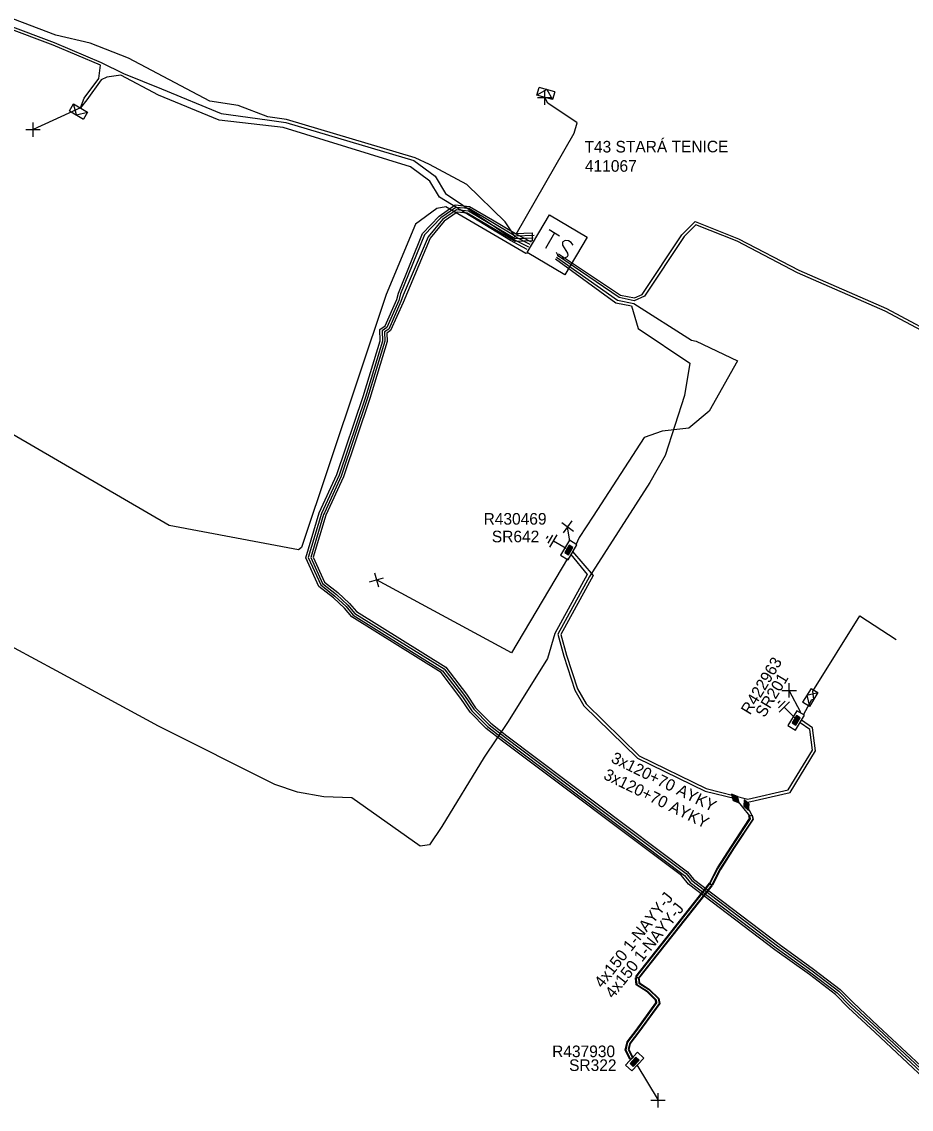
# Model space of a CAD drawing. Extents: x -540466 to -537383, y -1184038 to -1179972.
# Drawn here: x -538183.7 to -538107, y -1180908.9 to -1180815.2 of the extents above; entities that cross this region are included whole.
import ezdxf

# ---------------------------------------------------------------- set-up
doc = ezdxf.new("R2010")
doc.units = 0
for name, color, linetype in [('Vrstva 1', 7, 'Continuous'), ('Vrstva 14', 7, 'Continuous'), ('Vrstva 15', 7, 'Continuous'), ('Vrstva 19', 7, 'Continuous'), ('Vrstva 20', 7, 'Continuous'), ('Vrstva 25', 7, 'Continuous'), ('Vrstva 26', 7, 'Continuous'), ('Vrstva 27', 7, 'Continuous'), ('Vrstva 28', 7, 'Continuous'), ('Vrstva 29', 7, 'Continuous'), ('Vrstva 30', 7, 'Continuous'), ('Vrstva 31', 7, 'Continuous'), ('Vrstva 34', 7, 'Continuous'), ('Vrstva 4', 7, 'Continuous'), ('Vrstva 5', 7, 'Continuous'), ('Vrstva 52', 7, 'Continuous'), ('Vrstva 59', 7, 'Continuous'), ('Vrstva 6', 7, 'Continuous'), ('Vrstva 8', 7, 'Continuous'), ('Vrstva 9', 7, 'Continuous')]:
    doc.layers.add(name, color=color, linetype=linetype)

# ---------------------------------------------------------------- blocks, each defined once
blk = doc.blocks.new('NN870')
at = {"layer": 'Vrstva 4'}
for points in [[(0, -0.251), (0.5, 0.001), (0, 0.249), (-0.5, 0.001), (0, -0.251)], [(0.37, -0.003), (0, 0.186), (-0.362, 0.001), (0, -0.188), (0.37, -0.003)], [(0.245, -0.003), (0, 0.123), (-0.252, -0.003), (0, -0.125), (0.245, -0.003)], [(0.122, -0.003), (0, 0.06), (-0.13, -0.003), (0, -0.062), (0.122, -0.003)]]:
    blk.add_lwpolyline(points, dxfattribs=at)
blk = doc.blocks.new('NN800')
at = {"layer": 'Vrstva 1'}
for points in [[(-0.442, 0.442), (0.442, -0.442)], [(-0.442, -0.442), (0.442, 0.442)]]:
    blk.add_lwpolyline(points, dxfattribs=at)
blk = doc.blocks.new('NN620')
at = {"layer": 'Vrstva 8'}
for points in [[(0.752, 0.004), (-0.748, 0.004)], [(-0.748, 0.004), (-0.748, -0.746)], [(0.752, -0.746), (0.752, 0.004)], [(-0.748, -0.746), (0.752, -0.746)], [(0.368, -0.18), (-0.376, -0.18)], [(-0.376, -0.18), (-0.376, -0.558)], [(-0.376, -0.558), (0.368, -0.558)], [(0.321, -0.227), (-0.329, -0.227)], [(-0.329, -0.227), (-0.329, -0.51)], [(-0.329, -0.51), (0.321, -0.51)], [(0.274, -0.274), (-0.281, -0.274)], [(-0.281, -0.274), (-0.281, -0.463)], [(-0.281, -0.463), (0.274, -0.463)], [(0.227, -0.321), (-0.234, -0.321)], [(-0.234, -0.321), (-0.234, -0.416)], [(-0.234, -0.416), (0.227, -0.416)], [(-0.193, -0.369), (0.185, -0.369)], [(0.227, -0.416), (0.227, -0.321)], [(0.274, -0.463), (0.274, -0.274)], [(0.321, -0.51), (0.321, -0.227)], [(0.368, -0.558), (0.368, -0.18)]]:
    blk.add_lwpolyline(points, dxfattribs=at)
blk = doc.blocks.new('NN630')
at = {"layer": 'Vrstva 9'}
for points in [[(-0.003, -0.7), (-0.703, 0)], [(-0.703, -0.7), (-0.703, 0), (0.697, 0), (0.697, -0.7)], [(-0.703, -0.7), (0.697, -0.7)], [(-0.003, -0.7), (0.697, 0)]]:
    blk.add_lwpolyline(points, dxfattribs=at)
blk = doc.blocks.new('NN810')
at = {"layer": 'Vrstva 14'}
for points in [[(0.004, -0.64), (0.004, -1.89)], [(0.629, -1.89), (-0.621, -1.89)], [(0.388, -2.2), (-0.399, -2.2)], [(0.004, -2.515), (-0.124, -2.515)], [(0.137, -2.515), (0.004, -2.515)]]:
    blk.add_lwpolyline(points, dxfattribs=at)
blk = doc.blocks.new('NN640')
at = {"layer": 'Vrstva 6'}
for points in [[(-1.89, 1.889), (1.889, 1.889)], [(-1.89, -1.89), (-1.89, 1.889)], [(1.889, 1.889), (1.889, -1.89)], [(-1.26, 0.787), (-0.221, 0.787)], [(-0.725, 0.787), (-0.725, -0.788)], [(1.197, 0.661), (0.945, 0.787), (0.661, 0.787), (0.409, 0.661), (0.283, 0.472), (0.283, 0.409), (0.409, 0.22), (1.133, -0.158), (1.259, -0.316), (1.259, -0.473), (1.133, -0.662), (0.913, -0.788), (0.629, -0.788), (0.503, -0.725), (0.283, -0.599)], [(1.889, -1.89), (-1.89, -1.89)]]:
    blk.add_lwpolyline(points, dxfattribs=at)

msp = doc.modelspace()

# ---------------------------------------------------------------- linework, layer by layer
at = {"layer": 'Vrstva 20'}
msp.add_lwpolyline([(-538105.459, -1180906.69), (-538110.094, -1180902.33), (-538112.43, -1180900.175), (-538113.51, -1180899.055), (-538115.769, -1180897.331), (-538118.749, -1180895.181), (-538126.19, -1180889.528), (-538126.806, -1180888.797), (-538142.223, -1180877.218), (-538143.65, -1180876.105), (-538145.023, -1180874.711), (-538145.833, -1180873.515), (-538147.535, -1180871.285), (-538155.231, -1180866.498), (-538155.849, -1180865.747), (-538156.815, -1180864.858), (-538158.063, -1180863.87), (-538159.19, -1180861.402), (-538158.032, -1180857.524), (-538156.509, -1180854.209), (-538154.245, -1180847.498), (-538152.782, -1180842.691), (-538152.816, -1180841.724), (-538152.359, -1180841.419), (-538151.35, -1180839.148), (-538151.207, -1180838.588), (-538149.122, -1180833.444), (-538147.681, -1180831.951), (-538146.312, -1180830.991), (-538145.075, -1180831.108), (-538143.107, -1180832.272), (-538141.109, -1180833.452), (-538139.671, -1180833.378), (-538139.686, -1180834.085), (-538141.135, -1180834.136), (-538145.265, -1180831.692), (-538146.148, -1180831.609), (-538147.259, -1180832.389), (-538148.478, -1180833.846), (-538150.81, -1180839.411), (-538151.881, -1180841.821), (-538152.204, -1180842.037), (-538152.178, -1180842.769), (-538153.675, -1180847.682), (-538155.951, -1180854.431), (-538157.468, -1180857.736), (-538158.55, -1180861.358), (-538157.577, -1180863.49), (-538156.425, -1180864.402), (-538155.411, -1180865.333), (-538154.829, -1180866.042), (-538147.125, -1180870.835), (-538145.347, -1180873.165), (-538144.557, -1180874.329), (-538143.25, -1180875.655), (-538141.857, -1180876.742), (-538126.27, -1180888.482), (-538125.77, -1180889.092), (-538118.391, -1180894.699), (-538115.411, -1180896.849), (-538113.11, -1180898.605), (-538112.403, -1180899.318), (-538112.01, -1180899.745), (-538109.861, -1180901.729), (-538102.454, -1180908.641)], dxfattribs=at)
for points in [[(-538122.496, -1180886.248), (-538120.931, -1180883.882), (-538120.986, -1180883.655), (-538120.694, -1180883.585), (-538120.609, -1180883.938), (-538122.244, -1180886.41), (-538123.44, -1180888.275), (-538124.127, -1180889.609), (-538124.393, -1180889.471), (-538123.692, -1180888.113)], [(-538130.738, -1180897.487), (-538124.378, -1180889.447), (-538124.142, -1180889.633), (-538130.502, -1180897.673)], [(-538130.71, -1180902.11), (-538128.999, -1180899.753), (-538129.039, -1180899.523), (-538129.764, -1180898.808), (-538130.701, -1180898.208), (-538130.769, -1180897.597), (-538130.471, -1180897.563), (-538130.419, -1180898.032), (-538129.576, -1180898.572), (-538128.761, -1180899.377), (-538128.681, -1180899.827), (-538130.467, -1180902.287), (-538131.211, -1180903.256), (-538131.332, -1180903.773), (-538130.975, -1180904.515), (-538131.245, -1180904.645), (-538131.648, -1180903.807), (-538131.489, -1180903.124)]]:
    msp.add_lwpolyline(points, close=True, dxfattribs=at)
at = {"layer": 'Vrstva 5'}
for points in [[(-538139.854, -1180834.399), (-538141.153, -1180833.739), (-538142, -1180832.45), (-538145.31, -1180829.22), (-538148.52, -1180827.5), (-538149.774, -1180826.94), (-538160.867, -1180823.635), (-538162.455, -1180823.408), (-538165.03, -1180822.41), (-538167.46, -1180822.04), (-538174.47, -1180818.33), (-538177.79, -1180817.04), (-538180.73, -1180816.36), (-538193.95, -1180811.33)], [(-538140.114, -1180834.825), (-538141.55, -1180834.04), (-538147.67, -1180830.31), (-538148.49, -1180828.93), (-538150.16, -1180827.71), (-538161.15, -1180824.3), (-538166.65, -1180823.69), (-538171.88, -1180821.53), (-538175.141, -1180819.813), (-538176.36, -1180819.97), (-538176.828, -1180820.217), (-538178.08, -1180821.916), (-538178.604, -1180822.632), (-538178.291, -1180821.787), (-538177.048, -1180820.102), (-538176.897, -1180818.948), (-538180.977, -1180817.226), (-538185.023, -1180815.687)], [(-538184.937, -1180815.453), (-538180.883, -1180816.994), (-538176.831, -1180818.705), (-538174.924, -1180819.647), (-538171.625, -1180820.986), (-538166.499, -1180823.103), (-538162.53, -1180823.65), (-538160.92, -1180823.88), (-538149.887, -1180827.167), (-538148.037, -1180828.518), (-538147.154, -1180830.004), (-538141.267, -1180833.961), (-538139.984, -1180834.612)], [(-538139.507, -1180833.618), (-538141.127, -1180833.68), (-538145.138, -1180831.303), (-538146.257, -1180831.197), (-538147.54, -1180832.097), (-538148.951, -1180833.555), (-538151.017, -1180838.651), (-538151.17, -1180839.236), (-538152.2, -1180841.553), (-538152.612, -1180841.828), (-538152.581, -1180842.717), (-538154.055, -1180847.559), (-538156.323, -1180854.283), (-538157.844, -1180857.595), (-538158.977, -1180861.387), (-538157.901, -1180863.743), (-538156.685, -1180864.706), (-538155.703, -1180865.609), (-538155.097, -1180866.346), (-538147.398, -1180871.135), (-538145.671, -1180873.398), (-538144.868, -1180874.584), (-538143.517, -1180875.955), (-538142.101, -1180877.059), (-538133.77, -1180883.33), (-538126.55, -1180888.773), (-538126.05, -1180889.383), (-538118.63, -1180895.02), (-538115.65, -1180897.17), (-538113.377, -1180898.905), (-538112.29, -1180900.032), (-538109.958, -1180902.183), (-538102.729, -1180908.933)], [(-538139.587, -1180833.85), (-538141.136, -1180833.907), (-538143.311, -1180832.616), (-538145.152, -1180831.529), (-538146.203, -1180831.403), (-538147.4, -1180832.243), (-538148.65, -1180833.74), (-538150.81, -1180838.77), (-538150.99, -1180839.324), (-538152.04, -1180841.687), (-538152.408, -1180841.932), (-538152.379, -1180842.743), (-538153.865, -1180847.621), (-538156.137, -1180854.357), (-538157.583, -1180857.531), (-538157.656, -1180857.665), (-538158.763, -1180861.373), (-538157.739, -1180863.617), (-538156.555, -1180864.554), (-538155.557, -1180865.471), (-538154.963, -1180866.194), (-538147.262, -1180870.985), (-538145.509, -1180873.282), (-538144.712, -1180874.456), (-538143.383, -1180875.805), (-538141.979, -1180876.901), (-538133.65, -1180883.17), (-538126.41, -1180888.627), (-538125.919, -1180889.214), (-538118.51, -1180894.86), (-538115.53, -1180897.01), (-538113.243, -1180898.755), (-538112.15, -1180899.888), (-538109.822, -1180902.037), (-538102.591, -1180908.787)], [(-538052.907, -1180863.315), (-538058.518, -1180862.968), (-538063.136, -1180863.457), (-538064.164, -1180863.575), (-538074.521, -1180863.415), (-538076.257, -1180863.12), (-538078.004, -1180862.308), (-538084.893, -1180857.196), (-538088.786, -1180856.338), (-538092.426, -1180854.201), (-538095.531, -1180851.256), (-538097.76, -1180848.657), (-538103.883, -1180842.983), (-538109.225, -1180840.133), (-538116.784, -1180836.833), (-538122.002, -1180834.124), (-538125.57, -1180832.707), (-538126.583, -1180833.72), (-538129.996, -1180838.859), (-538130.867, -1180839.242), (-538132.185, -1180838.973), (-538137.489, -1180835.333)], [(-538137.402, -1180835.209), (-538132.055, -1180838.76), (-538130.851, -1180839.002), (-538130.204, -1180838.721), (-538126.777, -1180833.56), (-538125.63, -1180832.413), (-538121.898, -1180833.896), (-538116.676, -1180836.607), (-538109.115, -1180839.907), (-538103.737, -1180842.777), (-538097.58, -1180848.483), (-538095.349, -1180851.084), (-538092.274, -1180853.999), (-538088.694, -1180856.102), (-538084.787, -1180856.964), (-538077.876, -1180862.092), (-538076.183, -1180862.88), (-538074.499, -1180863.165), (-538064.176, -1180863.325), (-538063.162, -1180863.209), (-538058.503, -1180862.716), (-538052.893, -1180863.065)], [(-538137.669, -1180835.645), (-538132.465, -1180839.412), (-538131.098, -1180839.687), (-538130.54, -1180841.65), (-538126.08, -1180844.62), (-538126.53, -1180847.42), (-538128.22, -1180852.59), (-538129.54, -1180854.9), (-538134.745, -1180863.004), (-538137.46, -1180867.97), (-538136.949, -1180869.879), (-538135.995, -1180872.801), (-538135.23, -1180874.157), (-538130.603, -1180878.663), (-538124.763, -1180881.528), (-538122.15, -1180882.15)], [(-538137.582, -1180835.483), (-538132.315, -1180839.187), (-538130.921, -1180839.47), (-538125.94, -1180842.63), (-538125.53, -1180842.74), (-538121.98, -1180844.43), (-538124.42, -1180848.77), (-538126.18, -1180850.24), (-538128.46, -1180850.5), (-538130.02, -1180851.03), (-538134.423, -1180857.821), (-538135.616, -1180859.662), (-538135.899, -1180860.286)], [(-538136.327, -1180861.123), (-538134.936, -1180862.83), (-538137.727, -1180867.938), (-538138.35, -1180870.08), (-538141.74, -1180875.5), (-538143.8, -1180878.6), (-538147.45, -1180884.55), (-538148.53, -1180886.13), (-538149.32, -1180886.25), (-538155.22, -1180882.09), (-538157.63, -1180882.01), (-538159.9, -1180881.59), (-538161.85, -1180880.95), (-538171.88, -1180875.92), (-538180.69, -1180871.14), (-538191.58, -1180865.29), (-538196.46, -1180862.39), (-538201.87, -1180859.61), (-538209.46, -1180856.04), (-538209.85, -1180856.45)], [(-538136.196, -1180860.846), (-538134.411, -1180862.914), (-538137.193, -1180868.002), (-538136.711, -1180869.801), (-538135.765, -1180872.699), (-538135.03, -1180874.003), (-538130.457, -1180878.457), (-538124.677, -1180881.292), (-538121.069, -1180882.211), (-538117.599, -1180881.4), (-538115.509, -1180877.972), (-538115.727, -1180876.201), (-538116.574, -1180875.62)], [(-538121.2, -1180882.72), (-538121.071, -1180882.469), (-538117.441, -1180881.62), (-538115.251, -1180878.028), (-538115.493, -1180876.059), (-538116.445, -1180875.406)], [(-538122.15, -1180882.15), (-538120.937, -1180883.643), (-538120.877, -1180883.891), (-538122.454, -1180886.275), (-538123.657, -1180888.15), (-538124.344, -1180889.486), (-538130.724, -1180897.55), (-538130.654, -1180898.178), (-538129.733, -1180898.769), (-538128.993, -1180899.499), (-538128.946, -1180899.766), (-538130.67, -1180902.14), (-538131.442, -1180903.146), (-538131.595, -1180903.802), (-538131.2, -1180904.623)], [(-538121.2, -1180882.72), (-538120.743, -1180883.597), (-538120.663, -1180883.929), (-538122.286, -1180886.385), (-538123.483, -1180888.25), (-538124.176, -1180889.594), (-538130.516, -1180897.61), (-538130.466, -1180898.062), (-538129.607, -1180898.611), (-538128.807, -1180899.401), (-538128.734, -1180899.814), (-538130.51, -1180902.26), (-538131.258, -1180903.234), (-538131.385, -1180903.778), (-538131.02, -1180904.537)]]:
    msp.add_lwpolyline(points, dxfattribs=at)
at = {"layer": 'Vrstva 52'}
for points in [[(-538140.058, -1180835.148), (-538140.233, -1180835.183), (-538147.117, -1180831.163), (-538147.886, -1180831.303), (-538149.738, -1180832.631), (-538152.255, -1180838.713), (-538159.551, -1180860.516), (-538159.813, -1180860.726), (-538170.979, -1180858.629), (-538203.732, -1180839.555), (-538255.276, -1180815.843), (-538315.533, -1180788.947), (-538320.251, -1180784.7), (-538320.133, -1180782.695), (-538316.241, -1180773.965)], [(-538139.723, -1180834.185), (-538141.04, -1180833.516), (-538136.05, -1180824.8), (-538135.79, -1180823.91), (-538138.31, -1180822.21), (-538138.593, -1180821.723)]]:
    msp.add_lwpolyline(points, dxfattribs=at)
at = {"layer": 'Vrstva 59'}
for points in [[(-538178.604, -1180822.632), (-538182.706, -1180824.495)], [(-538136.423, -1180859.973), (-538136.623, -1180858.73)], [(-538136.622, -1180861.465), (-538141.461, -1180869.601), (-538153.095, -1180863.302)], [(-538116.263, -1180874.868), (-538115.57, -1180873.623), (-538115.398, -1180873.623), (-538115.487, -1180872.893), (-538111.434, -1180866.394), (-538108.287, -1180868.443)], [(-538116.524, -1180874.722), (-538117.517, -1180872.831)], [(-538130.65, -1180905.111), (-538128.822, -1180908.164)]]:
    msp.add_lwpolyline(points, dxfattribs=at)

# ---------------------------------------------------------------- block references
at = {"layer": 'Vrstva 15'}
for p, rotation in [((-538136.2, -1180860.92), -120.76271950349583), ((-538116.595, -1180875.606), -135)]:
    msp.add_blockref('NN810', p, dxfattribs=dict(at, rotation=rotation))
at = {"layer": 'Vrstva 19'}
for p, rotation in [((-538122.15, -1180882.15), -48.29396395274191), ((-538121.2, -1180882.72), -68.19859156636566)]:
    msp.add_blockref('NN870', p, dxfattribs=dict(at, rotation=rotation))
at = {"layer": 'Vrstva 25', "rotation": -30.55966953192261}
msp.add_blockref('NN640', (-538137.514, -1180834.427), dxfattribs=at)
at = {"layer": 'Vrstva 28'}
for p, rotation in [((-538136.201, -1180860.92), -120.743435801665), ((-538116.595, -1180875.606), -121.04442502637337), ((-538131.111, -1180904.58), 47.0763083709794)]:
    msp.add_blockref('NN620', p, dxfattribs=dict(at, rotation=rotation))
at = {"layer": 'Vrstva 31'}
for p, rotation in [((-538138.593, -1180821.723), 164.79023058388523), ((-538178.604, -1180822.632), -30.732363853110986), ((-538115.398, -1180873.623), -121.56437499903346)]:
    msp.add_blockref('NN630', p, dxfattribs=dict(at, rotation=rotation))
at = {"layer": 'Vrstva 34'}
for p, rotation in [((-538138.593, -1180821.723), 45), ((-538182.706, -1180824.495), 45), ((-538136.623, -1180858.73), -80.86660686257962), ((-538153.095, -1180863.302), -28.43486788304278), ((-538117.517, -1180872.83), 45), ((-538128.822, -1180908.164), 45)]:
    msp.add_blockref('NN800', p, dxfattribs=dict(at, rotation=rotation))

# ---------------------------------------------------------------- texts
at = {"layer": 'Vrstva 26'}
msp.add_text('411067', height=1, dxfattribs=at).set_placement((-538135.122, -1180828.126))
at = {"layer": 'Vrstva 27'}
msp.add_text('T43 STARÁ TENICE', height=1, rotation=0.082, dxfattribs=at).set_placement((-538135.162, -1180826.471))
at = {"layer": 'Vrstva 29'}
for s, rotation, p in [('R430469', 0.018, (-538143.862, -1180858.544)), ('R422963', 58.956, (-538120.886, -1180875.004))]:
    msp.add_text(s, height=1, rotation=rotation, dxfattribs=at).set_placement(p)
msp.add_text('R437930', height=1, dxfattribs=at).set_placement((-538137.953, -1180904.442))
at = {"layer": 'Vrstva 30'}
for s, rotation, p in [('SR642', 0.079, (-538143.15, -1180860.068)), ('SR201', 58.956, (-538119.642, -1180875.237))]:
    msp.add_text(s, height=1, rotation=rotation, dxfattribs=at).set_placement(p)
msp.add_text('SR322', height=1, dxfattribs=at).set_placement((-538136.49, -1180905.634))
at = {"layer": 'Vrstva 6'}
for s, rotation, p in [('3x120+70 AYKY', 333.873, (-538132.953, -1180878.985)), ('3x120+70 AYKY', 333.868, (-538133.601, -1180880.42)), ('4x150 1-NAYY-J', 51.65, (-538133.632, -1180898.544)), ('4x150 1-NAYY-J', 51.659, (-538132.698, -1180899.453))]:
    msp.add_text(s, height=1, rotation=rotation, dxfattribs=at).set_placement(p)

doc.saveas('drawing.dxf')
